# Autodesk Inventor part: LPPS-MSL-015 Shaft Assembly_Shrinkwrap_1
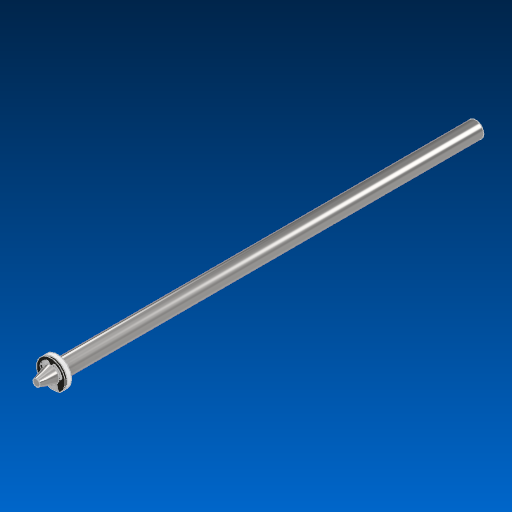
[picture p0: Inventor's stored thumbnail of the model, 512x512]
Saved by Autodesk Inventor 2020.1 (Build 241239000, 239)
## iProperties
Created: 2019-08
Part Number: LPPS-MSL-015 Shaft Assembly_Shrinkwrap_1
Material: Generic
Document SubType Name: Modeling
Designer: J. Nielson
Density: 1 g/cm^3
Appearance: Default
Author: J. Nielson
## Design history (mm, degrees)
node "Assembly1" dims "d0" = 10
body "Solid1"
node "Part1:1" dims "d0" = 10
node "Part2:1" dims "d0" = 10
body "Solid2"
node "Part3:1" dims "d0" = 10
body "Solid3"
